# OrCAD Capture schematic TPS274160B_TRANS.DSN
size C; title: TPS274160B: 40-V, 160-mOhm Quad-Channel Industrial Smart; rev: 1.0; note: Datasheet: SLVSF05     EVM: NA; note: High-Side Switch
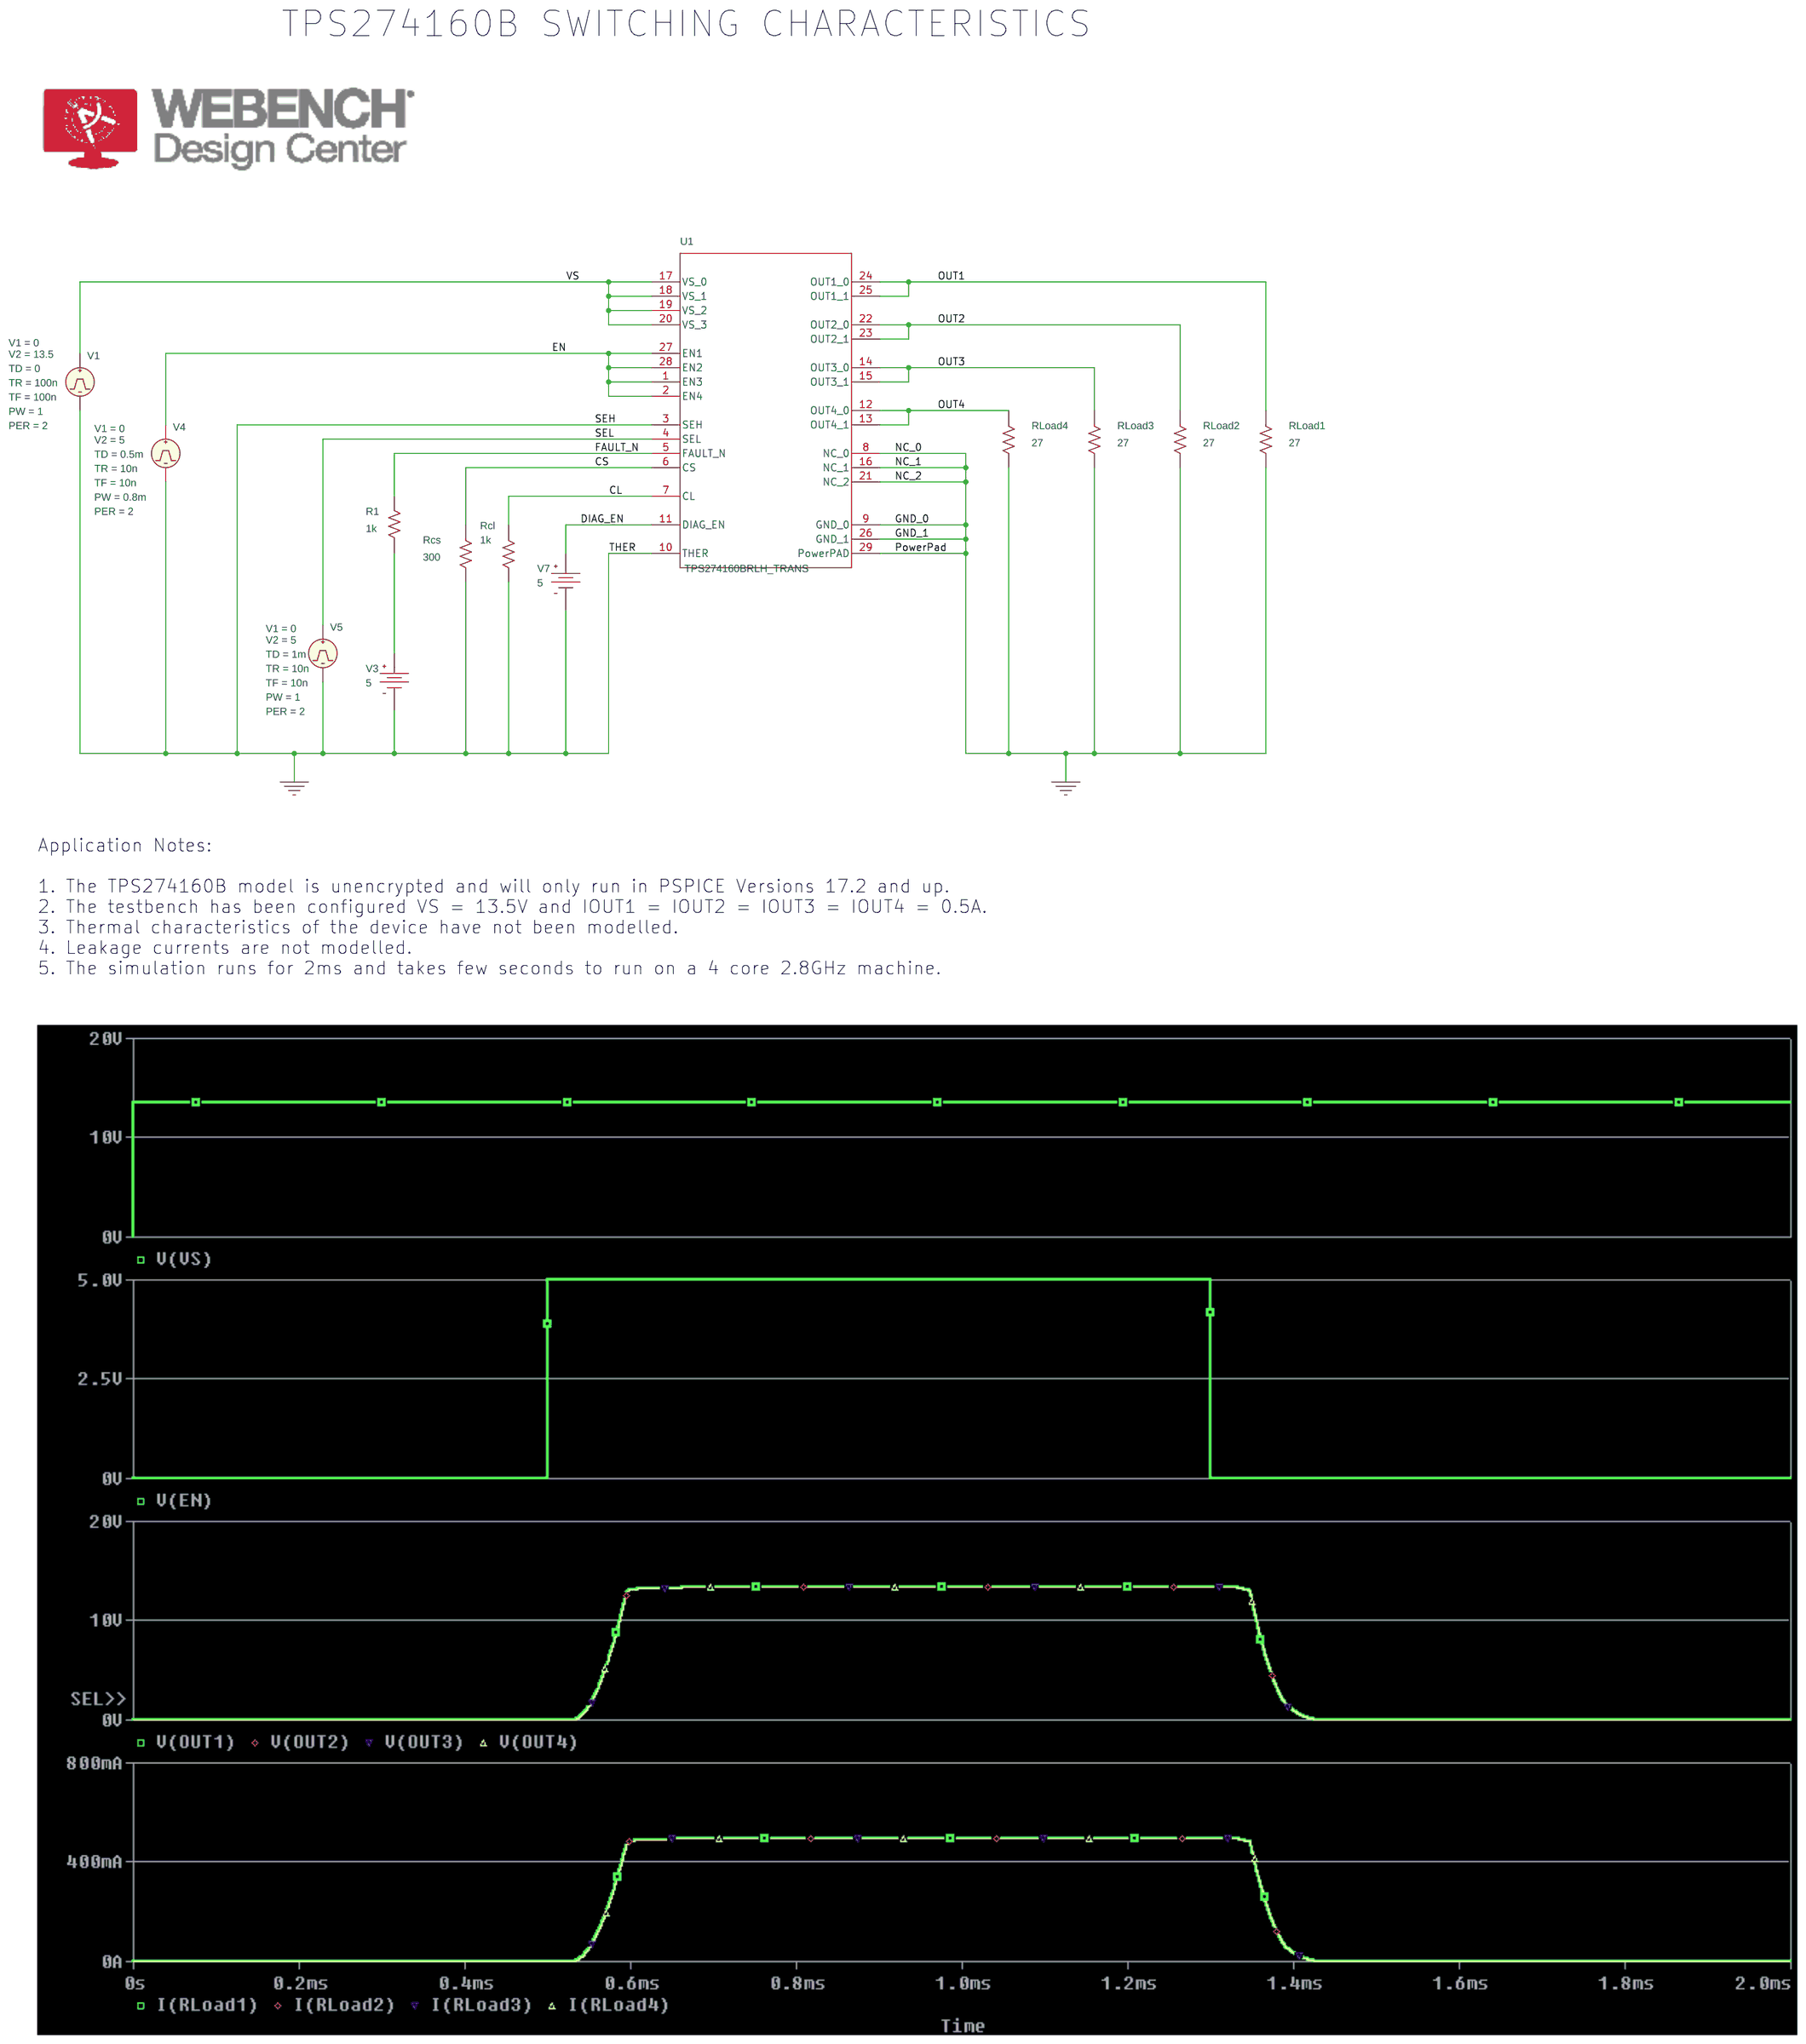
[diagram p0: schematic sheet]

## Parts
R1  1k  [AX/RC05]
Rcl  1k  [AX/RC05]
Rcs  300  [AX/RC05]
RLoad1  27  [AX/RC05]
RLoad2  27  [AX/RC05]
RLoad3  27  [AX/RC05]
RLoad4  27  [AX/RC05]
U1  TPS274160BRLH_TRANS  [RLH0028A-IPC_A]
V1  VPULSE
V3  VDC
V4  VPULSE
V5  VPULSE
V7  VDC

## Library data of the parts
R1 Rcl Rcs RLoad1-RLoad4 = R
U1 = TPS274160BRLH_TRANS
V1 = VPULSE: PER: 2; PW: 1; TD: 0; TF: 100n; TR: 100n; V1: 0; V2: 13.5
V3 V7 = VDC: DC: 5
V4 = VPULSE: PER: 2; PW: 0.8m; TD: 0.5m; TF: 10n; TR: 10n; V1: 0; V2: 5
V5 = VPULSE: PER: 2; PW: 1; TD: 1m; TF: 10n; TR: 10n; V1: 0; V2: 5

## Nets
0: Rcl.2 Rcs.2 RLoad1.2 RLoad2.2 RLoad3.2 RLoad4.2 U1.3(SEH) U1.8(NC_0) U1.9(GND_0) U1.10(THER) U1.16(NC_1) U1.21(NC_2) U1.26(GND_1) U1.29(PowerPAD) V1.2(-) V3.1(-) V4.2(-) V5.2(-) V7.1(-)
CL: Rcl.1 U1.7(CL)
CS: Rcs.1 U1.6(CS)
DIAG_EN: U1.11(DIAG_EN) V7.0(+)
EN: U1.1(EN3) U1.2(EN4) U1.27(EN1) U1.28(EN2) V4.1(+)
FAULT_N: R1.2 U1.5(FAULT_N)
OUT1: RLoad1.1 U1.24(OUT1_0) U1.25(OUT1_1)
OUT2: RLoad2.1 U1.22(OUT2_0) U1.23(OUT2_1)
OUT3: RLoad3.1 U1.14(OUT3_0) U1.15(OUT3_1)
OUT4: RLoad4.1 U1.12(OUT4_0) U1.13(OUT4_1)
SEL: U1.4(SEL) V5.1(+)
VS: U1.17(VS_0) U1.18(VS_1) U1.19(VS_2) U1.20(VS_3) V1.1(+)
N16825495: R1.1 V3.0(+)

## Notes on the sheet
- TPS274160B SWITCHING CHARACTERISTICS
- Application Notes:
  1. The TPS274160B model is unencrypted and will only run in PSPICE Versions 17.2 and up.
  2. The testbench has been configured VS = 13.5V and IOUT1 = IOUT2 = IOUT3 = IOUT4 = 0.5A.
  3. Thermal characteristics of the device have not been modelled.
  4. Leakage currents are not modelled.
  5. The simulation runs for 2ms and takes few seconds to run on a 4 core 2.8GHz machine.
